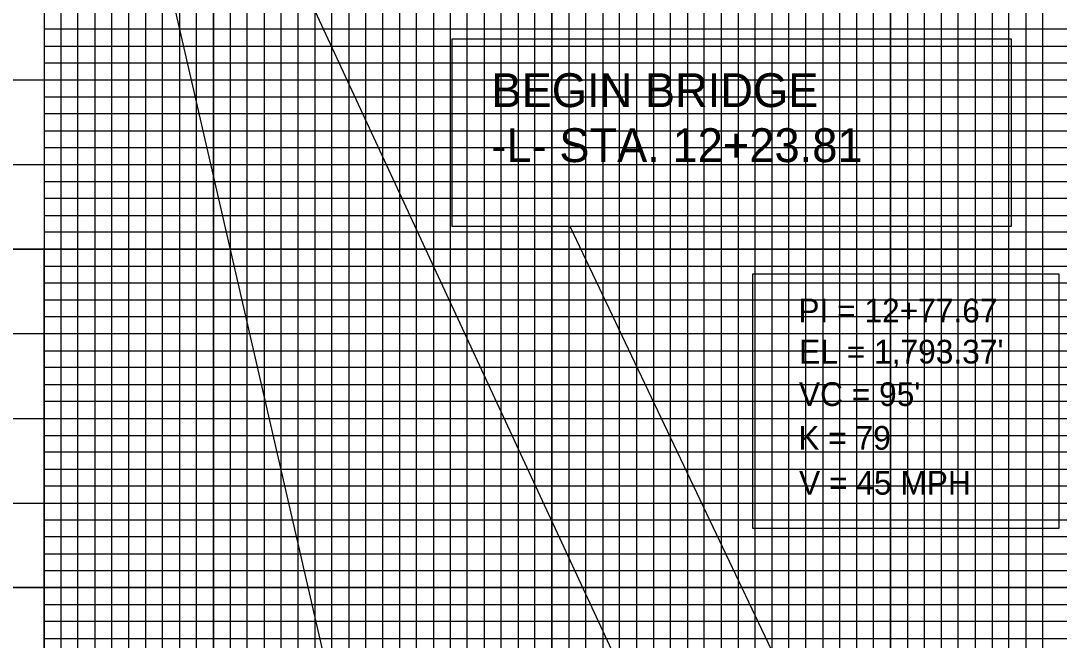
# Model space of a CAD drawing. Extents: x 572269 to 579912, y -56875 to -49627.
# Drawn here: x 573877.8 to 574184.5, y -53263.2 to -53080.2 of the extents above; entities that cross this region are included whole.
import ezdxf

# ---------------------------------------------------------------- set-up
doc = ezdxf.new("R2010")
doc.units = 0
for name, color, linetype in [('Exist Profile Cell', 7, 'Continuous'), ('Prop Grid Mask', 7, 'Continuous'), ('Prop PFL Text', 7, 'Continuous'), ('Prop Vertical Profile Curve Label', 7, 'Continuous'), ('Prop VPI Label', 7, 'Continuous'), ('Sheet Cutting Line CELL', 7, 'Continuous'), ('Sheet DOT Grid CELL', 7, 'Continuous'), ('Sheet Layout Profile Border', 7, 'Continuous'), ('Sheet Profile Grid Major CELL', 7, 'Continuous'), ('Sheet Profile Grid Middle CELL', 7, 'Continuous'), ('Sheet Profile Grid Minor CELL', 7, 'Continuous')]:
    doc.layers.add(name, color=color, linetype=linetype)

# ---------------------------------------------------------------- blocks, each defined once
blk = doc.blocks.new('PROFILE SHEET SINGLE')
at = {"layer": 'Sheet DOT Grid CELL'}
for p, q in [((1, 21), (1, 0.5)), ((2, 21), (2, 0.5)), ((3, 21), (3, 0.5)), ((4, 21), (4, 0.5)), ((5, 21), (5, 0.5)), ((6, 21), (6, 0.5)), ((0, 14.5), (30, 14.5)), ((0, 13.5), (30, 13.5)), ((0, 12.5), (30, 12.5)), ((0, 11.5), (30, 11.5))]:
    blk.add_line(p, q, dxfattribs=at)
at = {"layer": 'Sheet Profile Grid Major CELL'}
for points in [[(1, 21), (1, 0.5), (2, 0.5), (2, 21)], [(3, 21), (3, 0.5), (4, 0.5), (4, 21)], [(5, 21), (5, 0.5), (6, 0.5), (6, 21)], [(30, 13.5), (0, 13.5), (0, 14.5), (30, 14.5)], [(30, 11.5), (0, 11.5), (0, 12.5), (30, 12.5)]]:
    blk.add_lwpolyline(points, dxfattribs=at)
at = {"layer": 'Sheet Profile Grid Middle CELL'}
for points in [[(1.5, 0.5), (1.5, 21)], [(2.5, 21), (2.5, 0.5), (3.5, 0.5), (3.5, 21)], [(4.5, 21), (4.5, 0.5), (5.5, 0.5), (5.5, 21)], [(6.5, 21), (6.5, 0.5), (7.5, 0.5), (7.5, 21)], [(30, 15), (0, 15), (0, 14), (30, 14)], [(30, 13), (0, 13), (0, 12), (30, 12)]]:
    blk.add_lwpolyline(points, dxfattribs=at)
at = {"layer": 'Sheet Profile Grid Minor CELL'}
for points in [[(1.1, 21), (1.1, 0.5), (1.2, 0.5), (1.2, 21)], [(1.3, 21), (1.3, 0.5), (1.4, 0.5), (1.4, 21)], [(1.6, 21), (1.6, 0.5), (1.7, 0.5), (1.7, 21)], [(1.8, 21), (1.8, 0.5), (1.9, 0.5), (1.9, 21)], [(2.1, 21), (2.1, 0.5), (2.2, 0.5), (2.2, 21)], [(2.3, 21), (2.3, 0.5), (2.4, 0.5), (2.4, 21)], [(2.6, 21), (2.6, 0.5), (2.7, 0.5), (2.7, 21)], [(2.8, 21), (2.8, 0.5), (2.9, 0.5), (2.9, 21)], [(3.1, 21), (3.1, 0.5), (3.2, 0.5), (3.2, 21)], [(3.3, 21), (3.3, 0.5), (3.4, 0.5), (3.4, 21)], [(3.6, 21), (3.6, 0.5), (3.7, 0.5), (3.7, 21)], [(3.8, 21), (3.8, 0.5), (3.9, 0.5), (3.9, 21)], [(4.1, 21), (4.1, 0.5), (4.2, 0.5), (4.2, 21)], [(4.3, 21), (4.3, 0.5)], [(4.3, 0.5), (4.4, 0.5), (4.4, 21)], [(4.6, 21), (4.6, 0.5), (4.7, 0.5), (4.7, 21)], [(4.8, 21), (4.8, 0.5), (4.9, 0.5), (4.9, 21)], [(5.1, 21), (5.1, 0.5), (5.2, 0.5), (5.2, 21)], [(5.3, 21), (5.3, 0.5), (5.4, 0.5), (5.4, 21)], [(5.6, 21), (5.6, 0.5), (5.7, 0.5), (5.7, 21)], [(5.8, 21), (5.8, 0.5), (5.9, 0.5), (5.9, 21)], [(6.1, 21), (6.1, 0.5), (6.2, 0.5), (6.2, 21)], [(6.3, 21), (6.3, 0.5), (6.4, 0.5), (6.4, 21)], [(6.6, 21), (6.6, 0.5), (6.7, 0.5), (6.7, 21)], [(6.8, 21), (6.8, 0.5), (6.9, 0.5), (6.9, 21)], [(29, 14.8), (1, 14.8), (1, 14.7), (29, 14.7)], [(29, 14.6), (1, 14.6), (1, 14.4), (29, 14.4)], [(29, 14.3), (1, 14.3), (1, 14.2), (29, 14.2)], [(29, 14.1), (1, 14.1), (1, 13.9), (29, 13.9)], [(29, 13.8), (1, 13.8), (1, 13.7), (29, 13.7)], [(29, 13.6), (1, 13.6), (1, 13.4), (29, 13.4)], [(29, 13.3), (1, 13.3), (1, 13.2), (29, 13.2)], [(29, 13.1), (1, 13.1), (1, 12.9), (29, 12.9)], [(29, 12.8), (1, 12.8), (1, 12.7), (29, 12.7)], [(29, 12.6), (1, 12.6), (1, 12.4), (29, 12.4)], [(29, 12.3), (1, 12.3), (1, 12.2), (29, 12.2)], [(29, 12.1), (1, 12.1), (1, 11.9), (29, 11.9)], [(29, 11.8), (1, 11.8), (1, 11.7), (29, 11.7)], [(29, 11.6), (1, 11.6), (1, 11.4), (29, 11.4)], [(29, 11.3), (1, 11.3), (1, 11.2), (29, 11.2)]]:
    blk.add_lwpolyline(points, dxfattribs=at)

msp = doc.modelspace()

# ---------------------------------------------------------------- linework, layer by layer
at = {"layer": 'Exist Profile Cell'}
msp.add_line((573884.69, -53397.71), (573884.69, -53147.71), dxfattribs=at)
at = {"layer": 'Prop Grid Mask'}
for points in [[(574005.21, -53085.56), (574170.35, -53085.56), (574170.35, -53140.99), (574005.21, -53140.99)], [(574094.03, -53155.03), (574184.38, -53155.03), (574184.38, -53230.24), (574094.03, -53230.24)]]:
    msp.add_lwpolyline(points, close=True, dxfattribs=at)
at = {"layer": 'Prop PFL Text'}
for p, q in [((573974.87, -53300.26), (573900.84, -52978.52)), ((574064.36, -53291.86), (573958.57, -53063.91)), ((574109.43, -53286.8), (574040.04, -53140.99))]:
    msp.add_line(p, q, dxfattribs=at)
at = {"layer": 'Sheet Layout Profile Border'}
msp.add_lwpolyline([(573884.69, -52772.71), (573884.69, -53797.71), (575284.69, -53797.71), (575284.69, -52910.26), (575134.64, -52910.26), (575134.64, -52772.71)], close=True, dxfattribs=at)

# ---------------------------------------------------------------- block references
at = {"layer": 'Sheet Cutting Line CELL', "xscale": 50, "yscale": 50}
msp.add_blockref('PROFILE SHEET SINGLE', (573834.69, -53822.71), dxfattribs=at)

# ---------------------------------------------------------------- texts
at = {"layer": 'Prop PFL Text'}
for s, p in [('BEGIN BRIDGE', (574016.81, -53105.72)), ('-L- STA. 12+23.81', (574016.81, -53121.97))]:
    msp.add_text(s, height=10, dxfattribs=at).set_placement(p)
at = {"layer": 'Prop Vertical Profile Curve Label'}
for s, p in [("VC = 95'", (574107.65, -53194.03)), ('K = 79', (574107.47, -53206.95)), ('V = 45 MPH', (574107.69, -53220.23))]:
    msp.add_text(s, height=7, dxfattribs=at).set_placement(p)
at = {"layer": 'Prop VPI Label'}
for s, p in [('PI = 12+77.67', (574107.49, -53169.33)), ("EL = 1,793.37'", (574107.73, -53181.48))]:
    msp.add_text(s, height=7, dxfattribs=at).set_placement(p)

doc.saveas('drawing.dxf')
